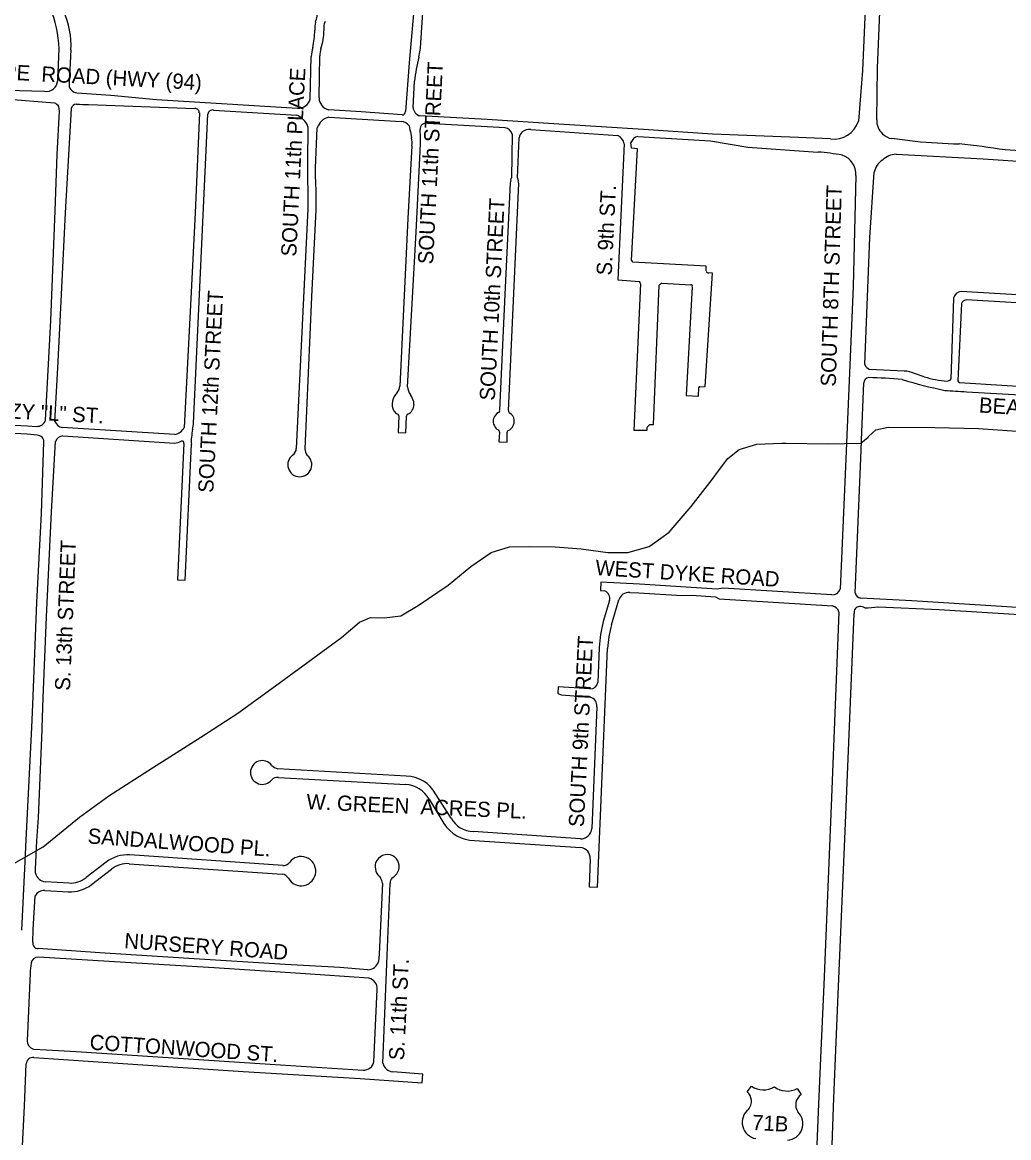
# Model space of a CAD drawing. Extents: x 0 to 712119, y 0 to 761125.
# Drawn here: x 683091 to 686331, y 723620 to 727282 of the extents above; entities that cross this region are included whole.
import ezdxf

# ---------------------------------------------------------------- set-up
doc = ezdxf.new("R2010")
doc.units = 0
for name, color, linetype in [('HWY signs', 7, 'Continuous'), ('PAVED ROADS', 7, 'Continuous'), ('stream or creek', 7, 'Continuous'), ('street names', 7, 'Continuous')]:
    doc.layers.add(name, color=color, linetype=linetype)

msp = doc.modelspace()

# ---------------------------------------------------------------- linework, layer by layer
at = {"layer": 'HWY signs'}
for points in [[(685471.5, 723770.9), (685486.6, 723789.4)], [(685561.5, 723787.4), (685561.5, 723787.4)], [(685636.2, 723781.6), (685649.3, 723761.7)]]:
    msp.add_lwpolyline(points, dxfattribs=at)
for centre, radius, start, end in [((685525.6, 723845.5), 68.4, 235.2382, 301.7199), ((685603.3, 723841.5), 68.4, 232.3011, 298.7827), ((685444.4, 723739.6), 41.5, 320.1078, 49.1208), ((685673, 723727.6), 41.5, 124.9002, 213.9131), ((685510.2, 723670.5), 54.5, 128.6765, 259.9158), ((685600.3, 723665.8), 54.5, 274.1051, 45.3444)]:
    msp.add_arc(centre, radius, start, end, dxfattribs=at)
at = {"layer": 'PAVED ROADS'}
for points in [[(685897.4, 726962.1), (685900, 727132.2), (685916.9, 727525.8), (685931.5, 727858.7), (685946, 728192.1), (685966.2, 728671.5), (685987, 729152), (685998.6, 729449.7)], [(685893.8, 728117.1), (685880.1, 727804.8), (685865.4, 727449.6), (685851, 727123.7), (685837.4, 726957)], [(684401.7, 727677.7), (684387.3, 727435.9), (684362.1, 727149.1), (684349.2, 726989.3)], [(684399.8, 727215.2), (684404.5, 727281), (684422.1, 727536.7), (684427, 727675.4)], [(683207.3, 727091.1), (683211.7, 727195)], [(683250.9, 727191.9), (683244.9, 727083.1)], [(684036.6, 727030.1), (684040.2, 727170.2)], [(684065.8, 727034), (684068, 727172.2)], [(681999.4, 727117.3), (682065.3, 727113.3), (682067.9, 727107.7), (682496.3, 727084.8), (682915.8, 727062.7), (683163.4, 727055.8)], [(684374.6, 727002.4), (684379.2, 727088.6)], [(683196.5, 727016.5), (682869.2, 727042.4), (682602.8, 727056.6)], [(683270.4, 727050.7), (683381.8, 727043.1), (683531.7, 727029.2), (683995.2, 727000.2)], [(683167.7, 725975.9), (683184.3, 726302.8), (683198.8, 726663.5), (683205.4, 726847.9), (683213.3, 726990.9), (683210.9, 727005.6)], [(683308.1, 727011.8), (683658.1, 726998.8)], [(683198.2, 725972), (683207.8, 726147.2), (683217.5, 726343.3), (683233.4, 726656.1), (683252.1, 726998.9)], [(683672.5, 726985), (683658.5, 726656.5), (683644.5, 726375.3), (683623, 725952.1)], [(683653.5, 725966.3), (683672.8, 726388.5), (683700.8, 726980.7)], [(683718.9, 726994), (683992.3, 726977.6)], [(684338.4, 726977.8), (684204.4, 726988.2), (684098.1, 726994.9)], [(684098.1, 726971.1), (684335.9, 726956.6)], [(685745.9, 726899.7), (685640.4, 726904.1), (685357.7, 726914.7), (685131, 726929.9), (684853.6, 726948), (684618.4, 726962.8), (684396.3, 726974.5)], [(684029.3, 726940.1), (684027.3, 726822.7), (684028.7, 726669.8), (683991, 725882.7)], [(684019.6, 725882.1), (684042.3, 726381.3), (684056.3, 726666), (684056.4, 726688.4), (684056.1, 726722.9), (684055, 726761), (684054.5, 726772.3), (684054.4, 726803.4), (684059.9, 726935.6)], [(684421.6, 726951), (684676.8, 726936.2)], [(684761, 726930.5), (685047.3, 726911)], [(684367.4, 726916.7), (684369, 726902.7)], [(684700.1, 726914.9), (684698.3, 726771.9)], [(684717.8, 726771.2), (684722.8, 726902.7)], [(685112.6, 726907.7), (685351, 726893.1), (685474.2, 726871.9), (685704.6, 726856.2)], [(686023.9, 726891.3), (685946.6, 726900.3)], [(684370.8, 726876.4), (684357.6, 726637.6), (684331.2, 726087.5)], [(684356.4, 726085.5), (684384.3, 726593.4), (684397.4, 726858.9)], [(685068.1, 726883.5), (685046.9, 726436.3), (685117.9, 726431.6)], [(685092.2, 726499.6), (685111.6, 726867.2), (685092.2, 726868.5), (685090.2, 726887.4)], [(687100.1, 726811.8), (686931.3, 726823.5), (686529.2, 726848.8), (686319.1, 726862.9)], [(685961, 726849.2), (686247.5, 726833.4), (686654.8, 726807), (687019.8, 726784.8), (687300.6, 726767.3), (687700.7, 726742.8), (688057.9, 726722), (688210.2, 726711.1)], [(685858, 726158.5), (685875.2, 726575.4), (685889.2, 726790.4)], [(684693.3, 726755.2), (684675.6, 726388.4), (684658.8, 726008.3)], [(684687.7, 726007.1), (684722.1, 726753.4)], [(685829.3, 726778.9), (685819.7, 726415.2), (685795.6, 725848.4), (685777.3, 725421)], [(685337.7, 726465.6), (685336.9, 726481.8), (685096.6, 726494.5)], [(685316.1, 726085.8), (685333.9, 726086.3), (685358.6, 726458.5), (685345.6, 726459.1)], [(685121.4, 726423.7), (685099.7, 725943.1), (685143.8, 725942.8), (685143.4, 725952.7)], [(685152.5, 725961.7), (685164.1, 725961.1), (685183, 726419.4)], [(685191.4, 726425.6), (685286.4, 726420.4)], [(685291.1, 726413.4), (685271.5, 726057), (685312.4, 726054.8), (685313.4, 726082.9)], [(686523.3, 726377.1), (686174.4, 726397.8)], [(686149.7, 726376), (686141.2, 726110.2)], [(686175.5, 726358.7), (686164.3, 726104.6)], [(686504.8, 726352.2), (686190.9, 726370.5)], [(685987.6, 726137.2), (685874, 726141.8)], [(686053.8, 726118.5), (686021.4, 726128.8)], [(685847.8, 725910.1), (685855, 726098.1)], [(686169.5, 726099), (686447.1, 726081.8)], [(686192.1, 726069.1), (686467.8, 726053.6)], [(682578.2, 725984.8), (682848.3, 725970.8), (683108.1, 725957.4), (683137.4, 725955.4)], [(684327.4, 725990.3), (684325.1, 725935), (684351, 725934.7), (684353.4, 725988.9)], [(683140.3, 725926.5), (683106.9, 725929.9), (682872.9, 725941.6), (682578.9, 725957.5)], [(683591.6, 725928.5), (683222.4, 725951.8)], [(683090, 724301.3), (683099.8, 724503.3), (683103.5, 724597.9), (683122.4, 724967), (683125.1, 725042.7), (683138.6, 725377.3), (683153.6, 725669), (683162.1, 725904.3)], [(683134.5, 724488.1), (683134.6, 724496), (683133.8, 724501.4), (683138.4, 724594.9), (683143.9, 724671.2), (683155.7, 724959.5), (683156, 724966.3), (683159.8, 725063.7), (683170.8, 725330.6), (683186.8, 725674.9), (683200.5, 725906.1)], [(683224.1, 725924.1), (683591.2, 725900.5)], [(684658, 725936.1), (684656.7, 725904.2), (684683.2, 725903.7), (684683.7, 725936.5)], [(685826.7, 725409), (685846.1, 725875.9), (685847.8, 725910.1)], [(683621.1, 725898.7), (683600.4, 725451.3), (683626.1, 725450.9), (683646.3, 725896.6)], [(685750.5, 725402.1), (685392.8, 725423.8), (685373.2, 725421.5), (685118, 725436.9), (684991.7, 725444.1), (684990.6, 725416.1), (685003.7, 725415)], [(685086.1, 725410.5), (685116.5, 725409.1), (685257.5, 725400.6), (685289.2, 725401.3), (685368, 725395.6), (685379.7, 725389), (685751.7, 725365.8)], [(686409.9, 725357.3), (686307.2, 725364.3), (686012.9, 725382.3), (685845.6, 725391.6)], [(685019.8, 725383.3), (684999.2, 725314.4)], [(685026.6, 725304), (685050.2, 725385.6)], [(685901.7, 725363), (686102.1, 725354), (686437.2, 725333.4)], [(685686.5, 722095.5), (685694.5, 722266), (685708.6, 722534.3), (685718.9, 722785.6), (685727, 723009), (685735.5, 723244), (685747.5, 723503.1), (685756.8, 723750.9), (685772.3, 724116.8), (685794.1, 724626.3), (685823.1, 725340.7)], [(685773.5, 725345.2), (685749.1, 724736.5), (685723.3, 724121.6), (685714.1, 723905.9), (685705.6, 723704.9), (685695.2, 723460.5)], [(684956.4, 724535), (684952.7, 724444), (684979.9, 724442.9), (685013.6, 725226.5)], [(684985.9, 725229.8), (684981.4, 725114.5)], [(684955.7, 725093.5), (684851.2, 725100.6), (684850, 725078.1), (684862.1, 725073.6), (684956.4, 725066.2)], [(684978, 725034.8), (684961.4, 724634.8)], [(684352.3, 724807), (683929.8, 724831.1)], [(683932.5, 724802.5), (684350.3, 724779.9)], [(684499.2, 724669.5), (684448.7, 724748.6)], [(684427.2, 724731.7), (684475.9, 724651.4)], [(684924.4, 724601.2), (684571.9, 724625.2)], [(684575.8, 724596.2), (684924.7, 724573.2)], [(683366.3, 724524.8), (683300.8, 724474)], [(683442.4, 724519.6), (683944.4, 724484.9)], [(683946.4, 724513.8), (683444.4, 724548.5)], [(683318.6, 724451.1), (683384.1, 724501.9)], [(683243.8, 724456.2), (683166.9, 724460.4)], [(684273.7, 724455.3), (684263.4, 724222.7), (684261.5, 724198)], [(684275.3, 723864.4), (684289.5, 724218.2), (684299.5, 724455.1)], [(683125.4, 724261.8), (683126.7, 724303.8), (683133.4, 724413.9)], [(683164.9, 724431.5), (683242.2, 724427.3)], [(684225.4, 724171.5), (684133.7, 724178.6), (683954.3, 724189.1), (683637.8, 724208.8), (683346, 724227.2), (683143.2, 724240.8)], [(684229.6, 724143.9), (684004.9, 724159.4), (683721, 724177.5), (683429.8, 724195), (683144.3, 724212.6)], [(683116.9, 724160.1), (683106.7, 723938.2)], [(684246, 723869.4), (684257, 724106.8)], [(683127.3, 723911), (683170.2, 723908.4), (683267.5, 723902.9), (683905.5, 723860.9), (684210.1, 723841.9)], [(683092, 723593.7), (683097.8, 723723.7), (683103.6, 723862.7)], [(683129, 723883.7), (683421.5, 723864.1), (683816.7, 723837.8), (684200.6, 723813.8), (684404.9, 723799.6), (684406.5, 723828.3), (684307.6, 723835.9)]]:
    msp.add_lwpolyline(points, dxfattribs=at)
for centre, radius, start, end in [((682847, 727185.6), 364.9, 1.4666, 23.3663), ((682979.7, 727205.5), 271.5, 357.1174, 24.4948), ((683983.3, 727312.7), 76.7, 336.4952, 7.641), ((684228.9, 727258.2), 176.9, 172.2303, 180.696), ((684141.9, 727262.3), 60.9, 158.3431, 186.6841), ((683658.5, 727276.6), 394.1, 348.6591, 357.0153), ((683852.8, 727267), 230.4, 341.8103, 349.6343), ((683844.6, 727255.7), 236.9, 352.6902, 359.8871), ((684142.4, 727168.6), 102.2, 162.6567, 179.1094), ((684361.9, 727135.9), 296.2, 168.4779, 172.9547), ((684151.4, 727223.9), 248.6, 346.8675, 358.0022), ((685049.9, 727007.3), 675.7, 166.2896, 173.0836), ((683169.6, 727092.9), 37.7, 260.4971, 357.1588), ((683272.5, 727078.6), 27.9, 170.6143, 265.699), ((683191.6, 726995.1), 22, 28.4971, 77.2752), ((683269, 726996.7), 17.1, 91.4901, 172.7838), ((683691.6, 735217), 8214.2, 267.04773, 267.32351), ((683997.2, 727040.9), 40.8, 267.0899, 344.6916), ((684105.8, 727034.2), 40, 180.2597, 259.0058), ((683659.4, 726985.7), 13.1, 357.0605, 95.6573), ((683715.9, 726979.1), 15.2, 78.734, 173.8671), ((683964.6, 726913.1), 70.2, 22.5919, 66.7336), ((684111.2, 726918.7), 54, 103.9707, 161.7112), ((684338.5, 726988.5), 10.7, 269.0994, 4.4035), ((684407, 727005.3), 32.5, 185.0847, 250.8738), ((684335.1, 726925.4), 31.2, 32.3907, 88.3879), ((684714.8, 727012.3), 360.3, 191.2396, 195.3873), ((683993.7, 726895.5), 405.3, 354.8223, 4.9023), ((684418.3, 726930.5), 20.7, 80.9124, 181.1031), ((684673.6, 726909.3), 27, 11.8019, 83.2674), ((684759, 726884.8), 45.7, 87.5824, 124.361), ((685757.1, 726983.4), 84.5, 262.3981, 341.8046), ((685956.8, 726960.4), 59.5, 178.3647, 227.7145), ((684306.3, 726885.1), 65.1, 352.3748, 15.6775), ((684751.1, 726900.5), 28.4, 129.0759, 175.4617), ((685028.3, 726875), 40.7, 12.0346, 62.0922), ((685120.7, 726876.2), 32.5, 104.3643, 159.78), ((685953, 726947.6), 47.7, 220.7885, 262.3628), ((686377.9, 731507.4), 4629.6, 265.6138, 267.3991), ((685918.4, 724364.5), 2530.4, 80.8893, 84.3421), ((685594.6, 725656.5), 1204.8, 80.9412, 84.7584), ((685759.9, 726781.2), 69.5, 358.1612, 69.4722), ((685954.5, 726774.7), 67.2, 124.8251, 166.46), ((685966.8, 726773.9), 75.5, 94.448, 132.1842), ((684736.2, 726749.8), 43.3, 160.7861, 172.7382), ((684665.1, 726779.7), 34.1, 332.5104, 346.7915), ((684833.5, 726794.3), 118, 191.2796, 195.9357), ((684674.6, 726746.6), 47.9, 8.0643, 18.5944), ((685101, 726502.7), 9.3, 199.0702, 241.3604), ((685345.9, 726467.5), 8.38, 193.1894, 268.0418), ((685111.1, 726424), 10.2, 358.6915, 48.4652), ((685251.5, 726335.9), 108, 123.8598, 129.3773), ((685287.3, 726416), 4.57, 325.7522, 101.6516), ((686176, 726371.1), 26.8, 93.4648, 169.444), ((686193.4, 726351.3), 19.4, 97.2891, 157.5477), ((685897.2, 726180), 44.7, 208.7372, 238.7885), ((685983.1, 726047.1), 90.2, 64.9359, 87.1556), ((684288.2, 726092.2), 43.3, 323.0358, 353.8242), ((685873.4, 726097.2), 18.5, 97.5693, 177.0886), ((685839, 724546.5), 1569.4, 84.8033, 88.8334), ((686436, 727597.1), 1555.6, 252.9997, 258.3092), ((686145.7, 726400.8), 296.9, 251.9681, 266.7794), ((686130.2, 726117.7), 13.4, 265.0536, 325.7301), ((686173.5, 726108), 9.78, 200.1109, 246.3462), ((684355.4, 726028.9), 49.5, 131.1839, 207.0238), ((684403.7, 726087.6), 47.4, 182.5662, 216.7861), ((684324.1, 726025.6), 53.5, 1.5883, 38.9385), ((685315.6, 726083.5), 2.31, 78.3416, 196.6158), ((686356.7, 729136), 3071.4, 265.5953, 266.9277), ((684343.9, 726027.1), 33.8, 292.9135, 0.0601), ((684351.8, 726040.9), 53.2, 220.4203, 238.5463), ((684321.8, 725990.4), 5.56, 358.541, 66.233), ((684360.9, 725989.5), 7.51, 120.8875, 184.3957), ((684670.9, 725972.3), 33.1, 119.4575, 207.5859), ((684654.1, 726006.2), 5.09, 275.9915, 24.4959), ((684695.4, 726006.2), 7.74, 173.6281, 247.9617), ((684677.3, 725973.8), 29.5, 6.2363, 58.9893), ((683138.6, 725986.3), 30.9, 267.7954, 340.2821), ((683228.3, 725983.4), 32.1, 200.8267, 259.4668), ((683583, 725972.6), 44.9, 281.0977, 332.8966), ((684006.8, 725893.7), 360.9, 171.6436, 175.8081), ((683580.5, 725969.7), 73.1, 341.2454, 357.4092), ((684663.4, 725965.3), 23.3, 200.8896, 245.8639), ((684652.1, 725938.1), 6.21, 341.1652, 73.8323), ((684687.8, 725937.5), 4.21, 100.0029, 193.2925), ((684672.2, 725972.8), 34.6, 295.4825, 6.8988), ((685171.1, 725933.6), 33.7, 123.4571, 145.3593), ((683140.3, 725904.6), 21.8, 359.1052, 89.9718), ((683225.5, 725897.8), 26.3, 93.1281, 161.7252), ((683580, 725977.8), 78.1, 278.2366, 295.1701), ((683615.6, 725901.4), 6.13, 333.6824, 112.3483), ((683740.1, 725906), 94.3, 171.4472, 185.7583), ((683964.9, 725883), 26.1, 301.9848, 359.4149), ((684047, 725879.3), 27.6, 174.0069, 223.9938), ((684002.4, 725829.5), 39.4, 127.0788, 51.1321), ((684994.7, 725390.6), 26.1, 343.8972, 69.7459), ((685083.6, 725375.7), 34.8, 85.7677, 163.4543), ((685751.5, 725429.2), 27.1, 267.8707, 342.5196), ((685847.4, 725412.5), 21, 189.5169, 265.1234), ((685748.6, 725340.7), 25.2, 10.1543, 83.0788), ((685843.8, 725343.7), 20.9, 97.91, 188.2943), ((685838.5, 725321), 43.5, 63.0739, 86.7364), ((685851.4, 725740.7), 381, 271.0235, 277.5845), ((685440.1, 725201.5), 455.1, 165.6323, 176.4346), ((685313, 725216.1), 299.6, 162.9311, 177.9988), ((684956.2, 725119.1), 25.6, 268.8733, 349.6707), ((684950.2, 725038.9), 28.1, 351.7523, 77.148), ((683879.4, 724819.1), 39, 36.6251, 322.6043), ((683944.4, 724877.2), 48.4, 225.9998, 252.5091), ((684350.8, 724695.7), 111.3, 28.3911, 89.1924), ((683928.5, 724777), 25.8, 81.1598, 134.5822), ((684342.6, 724682.2), 98, 30.3017, 85.5013), ((684575.1, 724712.2), 87.1, 209.3776, 267.8721), ((684575.2, 724713.2), 116.9, 211.862, 270.3395), ((684925, 724637.7), 36.5, 268.9644, 355.4587), ((684290.3, 724508), 41.5, 64.7192, 159.5991), ((684920.1, 724537.1), 36.4, 356.7612, 82.8141), ((683436.5, 724434.3), 114.5, 86.0466, 127.7832), ((683436.5, 724434.3), 85.5, 86.0466, 127.7832), ((683948.1, 724539.3), 25.5, 266.0466, 323.0754), ((684006.9, 724495.1), 48, 209.0178, 143.0754), ((684296.4, 724510.4), 46.5, 164.8748, 232.4293), ((684289.5, 724510.6), 39.5, 332.7097, 62.0813), ((683168.5, 724495.1), 34.7, 191.6313, 267.2953), ((683942.6, 724459.5), 25.5, 29.0178, 86.0466), ((684270.3, 724525.1), 63.4, 304.1912, 329.0592), ((683248.4, 724541.6), 114.5, 266.8694, 307.783), ((683248.4, 724541.6), 85.5, 266.8694, 307.783), ((684226.6, 724450.4), 47.4, 5.9114, 29.1355), ((684320.5, 724457.4), 21.1, 133.643, 186.384), ((683163.3, 724397.3), 34.2, 87.3655, 150.905), ((683143.3, 724258.9), 18.1, 170.8512, 269.8), ((683310.8, 724159.9), 193.9, 170.2156, 179.9396), ((683142.9, 724189.1), 23.5, 86.6063, 170.9055), ((684224.2, 724210.9), 39.4, 271.6789, 340.9047), ((684219, 724107.4), 38, 359.1485, 73.6952), ((683135.9, 723938.9), 29.2, 181.4415, 252.8351), ((683126.8, 723860.5), 23.3, 84.5846, 174.5304), ((684211.9, 723876.8), 34.9, 267.0943, 347.7086), ((684312.4, 723873.9), 38.3, 194.3723, 262.7343)]:
    msp.add_arc(centre, radius, start, end, dxfattribs=at)
at = {"layer": 'stream or creek'}
msp.add_lwpolyline([(683025.4, 724498.7), (683159.8, 724575.2), (683278.5, 724672.1), (683375.4, 724742.4), (683519.1, 724834.6), (683676.9, 724934.6), (683798.8, 725014.3), (683934.8, 725112.7), (684061.3, 725204.9), (684139.4, 725262.7), (684198.8, 725312.7), (684234.7, 725328.3), (684280.1, 725326.8), (684334.7, 725333), (684391, 725367.4), (684489.5, 725434.6), (684564.5, 725495.5), (684631.6, 725540.8), (684691, 725559.6), (684756.6, 725561.1), (684841, 725559.5), (684926.9, 725553.4), (685014.5, 725540.8), (685080.1, 725540.8), (685150.4, 725561.2), (685160.6, 725568.4), (685216, 725608), (685287.9, 725692.4), (685356.6, 725781.5), (685377.3, 725809), (685408.2, 725850.2), (685445.7, 725879.9), (685503.5, 725897.1), (685585.9, 725899.8), (685598.8, 725900.2), (685737.9, 725898.6), (685845.7, 725900.2), (685869.1, 725920.5), (685870.5, 725921.8), (685894.1, 725944), (685934.7, 725953.3), (686087.9, 725951.7), (686231.6, 725948.6), (686358.2, 725939.2)], dxfattribs=at)

# ---------------------------------------------------------------- texts
at = {"layer": 'HWY signs'}
msp.add_text('71B', height=50, rotation=357.0105, dxfattribs=at).set_placement((685487.2, 723645.5))
at = {"layer": 'street names'}
for s, rotation, p in [('WEST NEW HOPE  ROAD (HWY (94)', 356.8904, (682540.6, 727121.3)), ('SOUTH 11th STREET', 87.193, (684440.2, 726486.8)), ('SOUTH 11th PLACE', 87.193, (683990.8, 726512.1)), ('SOUTH 8TH STREET', 88.2731, (685763, 726085.7)), ('S. 9th ST.', 87.193, (685026.9, 726450.1)), ('SOUTH 10th STREET', 87.193, (684642.9, 726039.3)), ('SOUTH 12th STREET', 87.193, (683718.3, 725736.4)), ('BEACON', 356.38, (686232.3, 726001.2)), ('WEST LAZY "L" ST.', 356.9304, (682753.6, 725997.4)), ('S. 13th STREET', 87.7031, (683247.7, 725086.9)), ('WEST DYKE ROAD', 356.2816, (684972.2, 725467.6)), ('SOUTH 9th STREET', 87.193, (684935.4, 724638.9)), ('W. GREEN  ACRES PL.', 357.486, (684023.5, 724698.7)), ('SANDALWOOD PL.', 355.8536, (683304.4, 724586.3)), ('NURSERY ROAD', 355.8536, (683424.7, 724242.5)), ('S. 11th ST.', 87.193, (684344.7, 723873.1)), ('COTTONWOOD ST.', 356.1989, (683311.1, 723909.3))]:
    msp.add_text(s, height=50, rotation=rotation, dxfattribs=at).set_placement(p)

doc.saveas('drawing.dxf')
